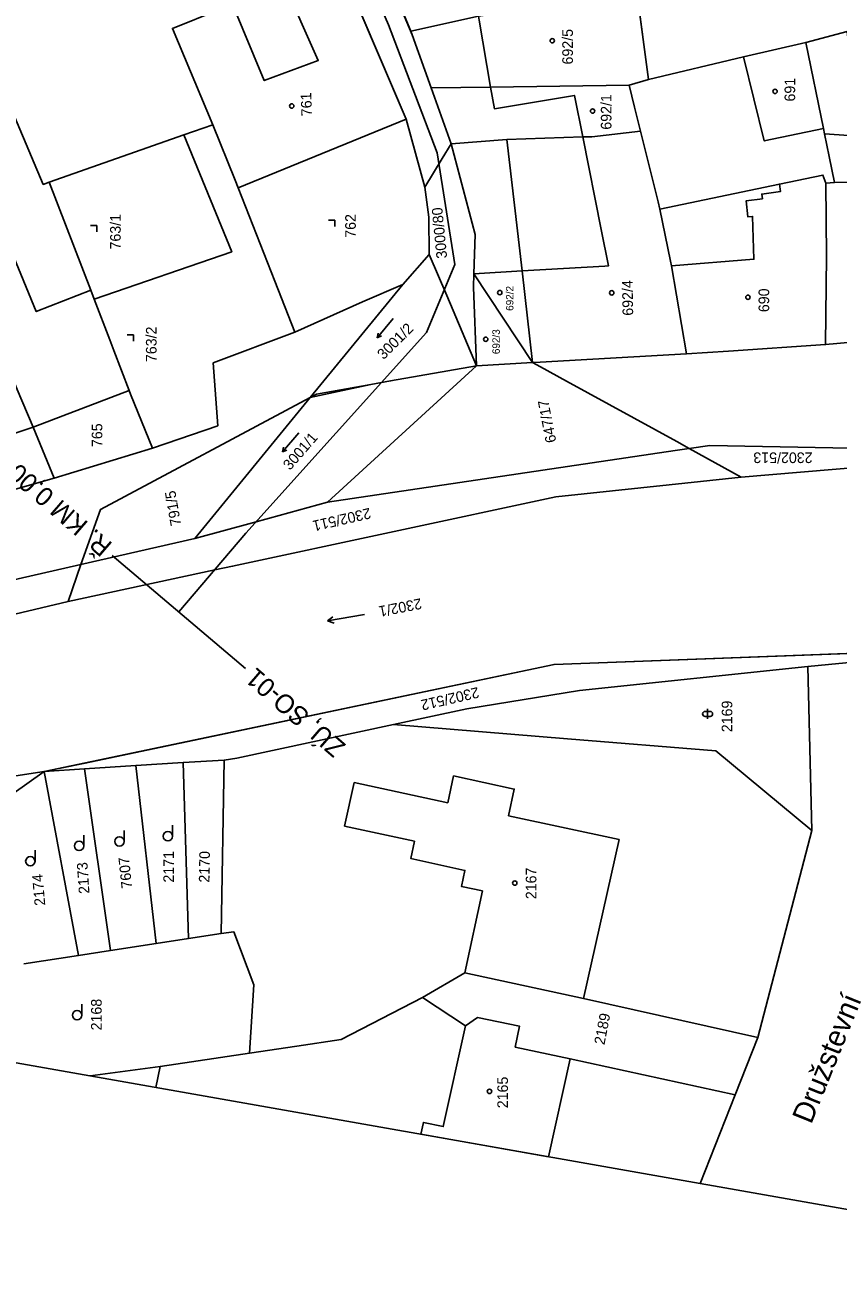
# Model space of a CAD drawing. Extents: x -534481 to -534262, y -1190577 to -1190138.
# Drawn here: x -534425.8 to -534360.6, y -1190577.1 to -1190477.8 of the extents above; entities that cross this region are included whole.
import ezdxf

# ---------------------------------------------------------------- set-up
doc = ezdxf.new("R2010")
doc.units = 0
for name, color, linetype in [('_KN_Město_Hluk', 7, 'Continuous'), ('_KN_Povodí_Moravy', 7, 'Continuous'), ('_N_osa', 7, 'Continuous'), ('_N_tenká', 7, 'Continuous'), ('_N_text', 7, 'Continuous'), ('_rámeček', 7, 'Continuous'), ('_rámeček_mřížka', 7, 'Continuous'), ('_tenka', 7, 'Continuous'), ('Hranice parcel', 7, 'Continuous'), ('Parcelní čísla', 7, 'Continuous'), ('Polygon budovy', 7, 'Continuous'), ('Pop  PČ popisy', 7, 'Continuous'), ('Značky budov', 7, 'Continuous'), ('Značky kultur', 7, 'Continuous')]:
    doc.layers.add(name, color=color, linetype=linetype)

msp = doc.modelspace()

# ---------------------------------------------------------------- linework, layer by layer
at = {"layer": '_KN_Město_Hluk'}
for p, q in [((-534393.4, -1190496.16), (-534395.53, -1190498.55)), ((-534395.53, -1190498.55), (-534402.95, -1190507.61)), ((-534389.63, -1190505.06), (-534391.5, -1190500.63)), ((-534396.5, -1190506.28), (-534389.63, -1190505.06))]:
    msp.add_line(p, q, dxfattribs=at)
for points in [[(-534391.5, -1190500.63), (-534392, -1190499.45), (-534393.4, -1190496.16)], [(-534402.95, -1190507.61), (-534398.08, -1190506.56), (-534396.5, -1190506.28)]]:
    msp.add_lwpolyline(points, dxfattribs=at)
at = {"layer": '_KN_Povodí_Moravy'}
for p, q in [((-534394.77, -1190478.57), (-534397.97, -1190470.9)), ((-534400.89, -1190472.11), (-534395.25, -1190485.32)), ((-534393.25, -1190482.82), (-534394.77, -1190478.57)), ((-534391.64, -1190487.29), (-534393.25, -1190482.82)), ((-534395.25, -1190485.32), (-534393.76, -1190490.76)), ((-534389.86, -1190498.78), (-534389.82, -1190497.69)), ((-534389.63, -1190505.06), (-534389.86, -1190498.78)), ((-534401.56, -1190515.98), (-534389.63, -1190505.06)), ((-534402.95, -1190507.61), (-534412.19, -1190518.9)), ((-534373.708, -1190511.857), (-534401.56, -1190515.98)), ((-534372.58, -1190511.69), (-534373.708, -1190511.857)), ((-534368.41, -1190513.97), (-534372.58, -1190511.69)), ((-534368.41, -1190513.97), (-534374.19, -1190514.588)), ((-534374.19, -1190514.588), (-534368.41, -1190513.97)), ((-534374.19, -1190514.588), (-534383.27, -1190515.56)), ((-534383.27, -1190515.56), (-534374.19, -1190514.588)), ((-534383.27, -1190515.56), (-534409.16, -1190521.11)), ((-534409.16, -1190521.11), (-534383.27, -1190515.56)), ((-534412.19, -1190518.9), (-534421.3, -1190520.98)), ((-534421.3, -1190520.98), (-534422.34, -1190523.93)), ((-534410.57, -1190521.41), (-534422.34, -1190523.93)), ((-534422.34, -1190523.93), (-534410.57, -1190521.41)), ((-534409.16, -1190521.11), (-534410.57, -1190521.41)), ((-534410.57, -1190521.41), (-534409.16, -1190521.11)), ((-534381.269, -1190528.899), (-534346.53, -1190527.59))]:
    msp.add_line(p, q, dxfattribs=at)
for points in [[(-534391.64, -1190487.29), (-534392.36, -1190488.47), (-534393.76, -1190490.76)], [(-534393.76, -1190490.76), (-534392.36, -1190488.47), (-534391.64, -1190487.29)], [(-534389.82, -1190497.69), (-534389.73, -1190494.54), (-534391.64, -1190487.29)], [(-534393.76, -1190490.76), (-534393.44, -1190493.16), (-534393.4, -1190496.16)], [(-534393.4, -1190496.16), (-534392, -1190499.45), (-534391.5, -1190500.63), (-534389.63, -1190505.06)], [(-534389.63, -1190505.06), (-534396.5, -1190506.28), (-534398.08, -1190506.56), (-534402.95, -1190507.61)], [(-534336.58, -1190512.09), (-534345.56, -1190512.439), (-534353.84, -1190512.76), (-534368.41, -1190513.97)], [(-534401.56, -1190515.98), (-534406.2, -1190517.26), (-534407.55, -1190517.63), (-534412.19, -1190518.9)], [(-534412.19, -1190518.9), (-534407.55, -1190517.63), (-534406.2, -1190517.26), (-534401.56, -1190515.98)], [(-534422.34, -1190523.93), (-534445.41, -1190529.41), (-534453.14, -1190531.2), (-534455.96, -1190531.85)], [(-534424.26, -1190537.56), (-534421.105, -1190536.897), (-534383.41, -1190528.98), (-534381.269, -1190528.899)], [(-534478.23, -1190550.17), (-534446.87, -1190541.01), (-534424.26, -1190537.56)]]:
    msp.add_lwpolyline(points, dxfattribs=at)
at = {"layer": '_N_osa'}
msp.add_line((-534408.105, -1190518.46), (-534413.469, -1190524.777), dxfattribs=at)
msp.add_lwpolyline([(-534408.105, -1190518.46), (-534393.616, -1190502.389), (-534391.346, -1190496.962), (-534392.763, -1190488.017), (-534396.655, -1190477.752), (-534402.513, -1190464.283), (-534404.757, -1190456.741), (-534408.311, -1190433.088), (-534409.248, -1190427.879), (-534409.316, -1190416.054), (-534409.076, -1190409.418), (-534409.868, -1190391.439)], dxfattribs=at)
at = {"layer": '_N_tenká'}
msp.add_line((-534408.133, -1190529.308), (-534418.805, -1190520.246), dxfattribs=at)
at = {"layer": '_rámeček'}
for points in [[(-534407.912, -1190137.674), (-534480.845, -1190551.293), (-534334.601, -1190577.08), (-534261.668, -1190163.461)], [(-534480.845, -1190551.293), (-534334.601, -1190577.08), (-534316.367, -1190473.675)]]:
    msp.add_lwpolyline(points, dxfattribs=at)
at = {"layer": '_rámeček_mřížka'}
msp.add_lwpolyline([(-534480.845, -1190551.293), (-534334.601, -1190577.08), (-534261.668, -1190163.461)], dxfattribs=at)
at = {"layer": '_tenka'}
for p, q in [((-534396.288, -1190501.278), (-534397.58, -1190502.818)), ((-534397.58, -1190502.818), (-534397.498, -1190502.459)), ((-534397.58, -1190502.818), (-534397.241, -1190502.675)), ((-534403.845, -1190510.435), (-534405.164, -1190511.952)), ((-534405.164, -1190511.952), (-534405.076, -1190511.594)), ((-534405.164, -1190511.952), (-534404.822, -1190511.815)), ((-534398.601, -1190524.977), (-534401.556, -1190525.497)), ((-534401.556, -1190525.497), (-534401.118, -1190525.166)), ((-534401.556, -1190525.497), (-534401.031, -1190525.66))]:
    msp.add_line(p, q, dxfattribs=at)
at = {"layer": 'Hranice parcel'}
for p, q in [((-534397.97, -1190470.9), (-534394.87, -1190478.28)), ((-534395.25, -1190485.32), (-534400.89, -1190472.11)), ((-534376.75, -1190475.31), (-534375.83, -1190482.13)), ((-534394.77, -1190478.57), (-534394.87, -1190478.28)), ((-534393.25, -1190482.82), (-534394.77, -1190478.57)), ((-534359.92, -1190478.31), (-534363.23, -1190479.17)), ((-534375.83, -1190482.13), (-534377.4, -1190482.59)), ((-534391.64, -1190487.29), (-534393.25, -1190482.82)), ((-534408.72, -1190490.82), (-534395.25, -1190485.32)), ((-534393.76, -1190490.76), (-534395.25, -1190485.32)), ((-534413.05, -1190486.57), (-534423.85, -1190490.37)), ((-534410.74, -1190485.76), (-534413.05, -1190486.57)), ((-534375.06, -1190491.94), (-534376.48, -1190486.28)), ((-534391.64, -1190487.29), (-534387.18, -1190486.94)), ((-534365.36, -1190490.52), (-534374.94, -1190492.52)), ((-534360.94, -1190490.38), (-534361.64, -1190490.44)), ((-534374.94, -1190492.52), (-534375.06, -1190491.94)), ((-534395.53, -1190498.55), (-534393.4, -1190496.16)), ((-534402.95, -1190507.61), (-534395.53, -1190498.55)), ((-534389.82, -1190497.69), (-534385.13, -1190504.81)), ((-534372.8, -1190504.12), (-534384.53, -1190504.78)), ((-534389.63, -1190505.06), (-534401.56, -1190515.98)), ((-534385.13, -1190504.81), (-534389.63, -1190505.06)), ((-534384.53, -1190504.78), (-534385.13, -1190504.81)), ((-534425.14, -1190509.99), (-534417.44, -1190507.05)), ((-534412.19, -1190518.9), (-534402.95, -1190507.61)), ((-534433.06, -1190512.55), (-534425.14, -1190509.99)), ((-534425.14, -1190509.99), (-534423.46, -1190514.06)), ((-534423.46, -1190514.06), (-534415.58, -1190511.65)), ((-534401.56, -1190515.98), (-534373.708, -1190511.857)), ((-534373.708, -1190511.857), (-534372.58, -1190511.69)), ((-534368.41, -1190513.97), (-534372.58, -1190511.69)), ((-534431.51, -1190516.35), (-534423.46, -1190514.06)), ((-534421.3, -1190520.98), (-534412.19, -1190518.9)), ((-534422.34, -1190523.93), (-534421.3, -1190520.98)), ((-534346.53, -1190527.59), (-534363.09, -1190529.14)), ((-534362.76, -1190542.27), (-534363.09, -1190529.14)), ((-534421.01, -1190537.35), (-534424.26, -1190537.56)), ((-534416.92, -1190537.08), (-534421.01, -1190537.35)), ((-534418.94, -1190551.89), (-534421.01, -1190537.35)), ((-534413.12, -1190536.84), (-534416.92, -1190537.08)), ((-534416.92, -1190537.08), (-534415.27, -1190551.33)), ((-534409.82, -1190536.63), (-534413.12, -1190536.84)), ((-534413.12, -1190536.84), (-534412.69, -1190550.93)), ((-534409.82, -1190536.63), (-534410.07, -1190550.53)), ((-534424.26, -1190537.56), (-534429.03, -1190540.95)), ((-534424.26, -1190537.56), (-534421.51, -1190552.29)), ((-534367.07, -1190558.85), (-534362.76, -1190542.27)), ((-534412.69, -1190550.93), (-534415.27, -1190551.33)), ((-534410.07, -1190550.53), (-534412.69, -1190550.93)), ((-534418.94, -1190551.89), (-534421.51, -1190552.29)), ((-534415.27, -1190551.33), (-534418.94, -1190551.89)), ((-534421.51, -1190552.29), (-534425.87, -1190552.96)), ((-534368.89, -1190563.45), (-534367.07, -1190558.85)), ((-534414.97, -1190561.18), (-534420.555, -1190561.924)), ((-534414.97, -1190561.18), (-534415.295, -1190562.851)), ((-534371.693, -1190570.54), (-534368.89, -1190563.45))]:
    msp.add_line(p, q, dxfattribs=at)
for points in [[(-534394.87, -1190478.28), (-534389.45, -1190477.08), (-534382.56, -1190476.12), (-534376.75, -1190475.31)], [(-534410.27, -1190476.57), (-534413.98, -1190478.05), (-534410.74, -1190485.76)], [(-534363.23, -1190479.17), (-534368.22, -1190480.34), (-534375.83, -1190482.13)], [(-534363.23, -1190479.17), (-534361.82, -1190486.07), (-534361.73, -1190486.49), (-534361.36, -1190488.3), (-534360.94, -1190490.38)], [(-534377.4, -1190482.59), (-534388.49, -1190482.75), (-534393.25, -1190482.82)], [(-534377.4, -1190482.59), (-534376.96, -1190484.36), (-534376.48, -1190486.28)], [(-534423.85, -1190490.37), (-534424.32, -1190490.54), (-534427.57, -1190482.9), (-534435.1, -1190485.93)], [(-534435.1, -1190485.93), (-534432.31, -1190492.91), (-534427.51, -1190504.26), (-534426.4, -1190506.96), (-534425.14, -1190509.99)], [(-534420.25, -1190499.72), (-534409.22, -1190495.94), (-534413.05, -1190486.57)], [(-534410.74, -1190485.76), (-534408.96, -1190490.21), (-534408.72, -1190490.82)], [(-534387.18, -1190486.94), (-534381.11, -1190486.74), (-534380.38, -1190486.72), (-534376.48, -1190486.28)], [(-534391.64, -1190487.29), (-534392.36, -1190488.47), (-534393.76, -1190490.76)], [(-534389.82, -1190497.69), (-534389.73, -1190494.54), (-534391.64, -1190487.29)], [(-534385.13, -1190504.81), (-534385.97, -1190497.46), (-534387.18, -1190486.94)], [(-534420.25, -1190499.72), (-534420.52, -1190499.02), (-534423.85, -1190490.37)], [(-534361.64, -1190490.44), (-534361.87, -1190489.79), (-534365.36, -1190490.52)], [(-534361.64, -1190490.44), (-534361.58, -1190496.28), (-534361.66, -1190503.37)], [(-534360.94, -1190490.38), (-534357.12, -1190490.37), (-534355.82, -1190490.37), (-534352.77, -1190490.36), (-534350.1, -1190490.36)], [(-534408.72, -1190490.82), (-534405.77, -1190498.29), (-534404.16, -1190502.37)], [(-534393.4, -1190496.16), (-534393.44, -1190493.16), (-534393.76, -1190490.76)], [(-534372.8, -1190504.12), (-534374.01, -1190497.07), (-534374.08, -1190496.69), (-534374.94, -1190492.52)], [(-534393.4, -1190496.16), (-534392, -1190499.45), (-534391.5, -1190500.63), (-534389.63, -1190505.06)], [(-534404.16, -1190502.37), (-534398.74, -1190499.95), (-534395.53, -1190498.55)], [(-534389.63, -1190505.06), (-534389.86, -1190498.78), (-534389.82, -1190497.69)], [(-534417.44, -1190507.05), (-534418.68, -1190503.83), (-534419, -1190502.99), (-534420.25, -1190499.72)], [(-534415.58, -1190511.65), (-534410.34, -1190509.87), (-534410.71, -1190504.84), (-534404.16, -1190502.37)], [(-534361.66, -1190503.37), (-534355.33, -1190502.8), (-534350.6, -1190502.38)], [(-534361.66, -1190503.37), (-534369.42, -1190503.89), (-534372.8, -1190504.12)], [(-534389.63, -1190505.06), (-534396.5, -1190506.28), (-534398.08, -1190506.56), (-534402.44, -1190507.34), (-534402.95, -1190507.61)], [(-534385.13, -1190504.81), (-534384.49, -1190505.16), (-534382.4, -1190506.3), (-534373.582, -1190511.14)], [(-534415.58, -1190511.65), (-534417.33, -1190507.33), (-534417.44, -1190507.05)], [(-534421.3, -1190520.98), (-534419.75, -1190516.57), (-534402.95, -1190507.61)], [(-534373.582, -1190511.14), (-534372.58, -1190511.69)], [(-534372.58, -1190511.69), (-534370.92, -1190511.44), (-534345.58, -1190511.92), (-534336.58, -1190512.09)], [(-534336.58, -1190512.09), (-534353.84, -1190512.76), (-534368.41, -1190513.97)], [(-534368.41, -1190513.97), (-534374.19, -1190514.588)], [(-534374.19, -1190514.588), (-534383.27, -1190515.56), (-534409.16, -1190521.11), (-534410.57, -1190521.41), (-534422.34, -1190523.93)], [(-534401.56, -1190515.98), (-534406.2, -1190517.26), (-534407.55, -1190517.63), (-534412.19, -1190518.9)], [(-534455.96, -1190531.85), (-534446.93, -1190526.83), (-534421.3, -1190520.98)], [(-534422.34, -1190523.93), (-534445.41, -1190529.41), (-534453.14, -1190531.2), (-534455.96, -1190531.85)], [(-534381.269, -1190528.899), (-534346.53, -1190527.59)], [(-534424.26, -1190537.56), (-534383.41, -1190528.98), (-534381.269, -1190528.899)], [(-534363.09, -1190529.14), (-534381.36, -1190531.06)], [(-534381.36, -1190531.06), (-534390.4, -1190532.54), (-534396.26, -1190533.8)], [(-534396.26, -1190533.8), (-534408.82, -1190536.48), (-534409.82, -1190536.63)], [(-534382.333, -1190534.934), (-534396.26, -1190533.8)], [(-534362.76, -1190542.27), (-534370.46, -1190535.9), (-534382.333, -1190534.934)], [(-534424.26, -1190537.56), (-534446.87, -1190541.01), (-534478.23, -1190550.17)], [(-534410.07, -1190550.53), (-534409.06, -1190550.38), (-534407.46, -1190554.62), (-534407.81, -1190560.11)], [(-534393.95, -1190555.65), (-534390.54, -1190553.66), (-534381.04, -1190555.72), (-534367.07, -1190558.85)], [(-534393.95, -1190555.65), (-534400.45, -1190559.02), (-534404, -1190559.55), (-534407.81, -1190560.11)], [(-534368.89, -1190563.45), (-534382.12, -1190560.55), (-534386.52, -1190559.61), (-534386.17, -1190557.95), (-534389.54, -1190557.26), (-534390.5, -1190557.91), (-534393.95, -1190555.65)], [(-534407.81, -1190560.11), (-534412.46, -1190560.81), (-534414.97, -1190561.18)]]:
    msp.add_lwpolyline(points, dxfattribs=at)
at = {"layer": 'Polygon budovy'}
msp.add_line((-534394.068, -1190566.594), (-534383.85, -1190568.396), dxfattribs=at)
for points in [[(-534413.98, -1190478.05), (-534410.74, -1190485.76), (-534408.96, -1190490.21), (-534408.72, -1190490.82), (-534395.25, -1190485.32), (-534400.89, -1190472.11), (-534405.17, -1190474.16), (-534402.3, -1190480.62), (-534406.62, -1190482.23), (-534409.2, -1190476.06), (-534410.27, -1190476.57)], [(-534389.45, -1190477.08), (-534389.41, -1190477.39), (-534388.49, -1190482.75), (-534388.19, -1190484.49), (-534381.78, -1190483.41), (-534381.11, -1190486.74), (-534380.38, -1190486.72), (-534376.48, -1190486.28), (-534376.96, -1190484.36), (-534377.4, -1190482.59), (-534375.83, -1190482.13), (-534376.75, -1190475.31), (-534382.56, -1190476.12)], [(-534361.82, -1190486.07), (-534361.73, -1190486.49), (-534349.66, -1190487.33), (-534349.79, -1190490.39), (-534340.49, -1190491.25), (-534340.26, -1190491.25), (-534339.53, -1190483.31), (-534346.59, -1190482.73), (-534357.01, -1190481.97), (-534359.56, -1190481.78), (-534359.92, -1190478.31), (-534363.23, -1190479.17)], [(-534368.22, -1190480.34), (-534366.57, -1190487.06), (-534361.82, -1190486.07), (-534363.23, -1190479.17)], [(-534435.1, -1190485.93), (-534432.31, -1190492.91), (-534429.79, -1190491.88), (-534429.85, -1190491.74), (-534428.8, -1190491.29), (-534424.88, -1190500.72), (-534420.52, -1190499.02), (-534423.85, -1190490.37), (-534424.32, -1190490.54), (-534427.57, -1190482.9)], [(-534381.11, -1190486.74), (-534379.63, -1190494.14), (-534379.04, -1190497.06), (-534379.33, -1190497.08), (-534385.97, -1190497.46), (-534389.82, -1190497.69), (-534389.86, -1190498.78), (-534389.63, -1190505.06), (-534385.13, -1190504.81), (-534384.53, -1190504.78), (-534372.8, -1190504.12), (-534374.01, -1190497.07), (-534374.08, -1190496.69), (-534374.94, -1190492.52), (-534375.06, -1190491.94), (-534376.48, -1190486.28), (-534380.38, -1190486.72)], [(-534361.87, -1190489.79), (-534365.36, -1190490.52), (-534365.27, -1190491.11), (-534366.77, -1190491.32), (-534366.72, -1190491.69), (-534368.03, -1190491.87), (-534367.89, -1190493.13), (-534367.51, -1190493.1), (-534367.39, -1190496.53), (-534374.01, -1190497.07), (-534372.8, -1190504.12), (-534369.42, -1190503.89), (-534361.66, -1190503.37), (-534361.58, -1190496.28), (-534361.64, -1190490.44)], [(-534361.66, -1190503.37), (-534355.33, -1190502.8), (-534350.6, -1190502.38), (-534350.57, -1190496.27), (-534352.95, -1190496.47), (-534354.79, -1190496.64), (-534354.9, -1190495.48), (-534355.71, -1190495.55), (-534355.82, -1190490.37), (-534357.12, -1190490.37), (-534360.94, -1190490.38), (-534361.64, -1190490.44), (-534361.58, -1190496.28)], [(-534400.19, -1190541.92), (-534394.59, -1190543.13), (-534394.89, -1190544.51), (-534390.54, -1190545.47), (-534390.82, -1190546.76), (-534389.15, -1190547.11), (-534390.54, -1190553.66), (-534381.04, -1190555.72), (-534378.2, -1190543), (-534387.05, -1190541.1), (-534386.59, -1190538.96), (-534391.46, -1190537.91), (-534391.92, -1190540.05), (-534399.41, -1190538.44)]]:
    msp.add_lwpolyline(points, close=True, dxfattribs=at)
msp.add_lwpolyline([(-534383.85, -1190568.396), (-534382.12, -1190560.55), (-534386.52, -1190559.61), (-534386.17, -1190557.95), (-534389.54, -1190557.26), (-534390.5, -1190557.91), (-534392.28, -1190565.98), (-534393.87, -1190565.65), (-534394.068, -1190566.594)], dxfattribs=at)
at = {"layer": 'Značky budov'}
for centre in [(-534383.548, -1190479.042), (-534365.7, -1190483.093), (-534404.422, -1190484.264), (-534380.316, -1190484.67), (-534387.753, -1190499.204), (-534378.789, -1190499.223), (-534367.875, -1190499.575), (-534388.88, -1190502.94), (-534386.551, -1190546.481), (-534388.578, -1190563.164)]:
    msp.add_circle(centre, 0.175, dxfattribs=at)
at = {"layer": 'Značky kultur'}
for p, q in [((-534400.971, -1190493.411), (-534401.471, -1190493.411)), ((-534400.971, -1190493.911), (-534400.971, -1190493.411)), ((-534420.035, -1190493.842), (-534420.535, -1190493.842)), ((-534420.035, -1190494.342), (-534420.035, -1190493.842)), ((-534417.097, -1190502.595), (-534417.597, -1190502.595)), ((-534417.097, -1190503.095), (-534417.097, -1190502.595)), ((-534370.903, -1190532.739), (-534371.303, -1190532.739)), ((-534371.303, -1190533.139), (-534370.903, -1190533.139)), ((-534371.103, -1190533.339), (-534371.103, -1190532.538)), ((-534417.851, -1190543.152), (-534417.851, -1190542.277)), ((-534413.968, -1190542.731), (-534413.968, -1190541.856)), ((-534421.078, -1190543.511), (-534421.078, -1190542.636)), ((-534424.984, -1190544.735), (-534424.984, -1190543.86)), ((-534421.238, -1190557.061), (-534421.238, -1190556.186))]:
    msp.add_line(p, q, dxfattribs=at)
for centre in [(-534421.453, -1190543.511), (-534418.227, -1190543.152), (-534414.343, -1190542.731), (-534425.359, -1190544.735), (-534421.614, -1190557.061)]:
    msp.add_circle(centre, 0.375, dxfattribs=at)
for centre, start, end in [((-534371.303, -1190532.939), 90, 270), ((-534370.903, -1190532.939), 270, 89.98789)]:
    msp.add_arc(centre, 0.2, start, end, dxfattribs=at)

# ---------------------------------------------------------------- texts
at = {"layer": '_N_text'}
for s, p in [('Ř. KM 0,000', (-534418.699, -1190519.326)), ('ZÚ, SO-01', (-534400.02, -1190535.416))]:
    msp.add_text(s, height=1.5, rotation=139.20506, dxfattribs=at).set_placement(p)
at = {"layer": '_tenka'}
for s, rotation, p in [('3000/80', 95.61322, (-534391.965, -1190496.439)), ('3001/2', 45, (-534397.061, -1190504.619)), ('3001/1', 49, (-534404.561, -1190513.482)), ('2302/1', 191, (-534394.095, -1190523.675))]:
    msp.add_text(s, height=0.85, rotation=rotation, dxfattribs=at).set_placement(p)
at = {"layer": 'Parcelní čísla'}
for s, height, rotation, p in [('692/5', 0.85, 90, (-534381.897, -1190480.94)), ('691', 0.85, 90, (-534364.092, -1190483.905)), ('761', 0.85, 92, (-534402.793, -1190485.067)), ('692/1', 0.85, 90, (-534378.808, -1190486.16)), ('763/1', 0.85, 90, (-534418.118, -1190495.753)), ('762', 0.85, 90, (-534399.286, -1190494.813)), ('692/4', 0.85, 91, (-534377.066, -1190501.048)), ('692/2', 0.595, 90, (-534386.659, -1190500.665)), ('690', 0.85, 90, (-534366.174, -1190500.77)), ('763/2', 0.85, 90, (-534415.247, -1190504.77)), ('692/3', 0.595, 90, (-534387.751, -1190504.133)), ('647/17', 0.85, 101, (-534383.217, -1190511.145)), ('765', 0.85, 90, (-534419.593, -1190511.573)), ('2302/513', 0.85, 180, (-534362.698, -1190512.003)), ('791/5', 0.85, 100, (-534413.263, -1190517.812)), ('2302/511', 0.85, 193, (-534398.192, -1190516.433)), ('2302/512', 0.85, 193, (-534389.518, -1190530.781)), ('2169', 0.85, 90, (-534369.127, -1190534.404)), ('2171', 0.85, 90, (-534413.853, -1190546.447)), ('2170', 0.85, 89, (-534411.013, -1190546.454)), ('2173', 0.85, 94, (-534420.617, -1190547.314)), ('7607', 0.85, 96, (-534417.197, -1190546.879)), ('2174', 0.85, 95, (-534424.159, -1190548.257)), ('2167', 0.85, 90, (-534384.821, -1190547.774)), ('2168', 0.85, 90, (-534419.644, -1190558.28)), ('2189', 0.85, 79, (-534379.372, -1190559.477)), ('2165', 0.85, 90, (-534387.1, -1190564.514))]:
    msp.add_text(s, height=height, rotation=rotation, dxfattribs=at).set_placement(p)
at = {"layer": 'Pop  PČ popisy'}
msp.add_text('Družstevní', height=1.7, rotation=68, dxfattribs=at).set_placement((-534362.807, -1190565.853))

doc.saveas('drawing.dxf')
